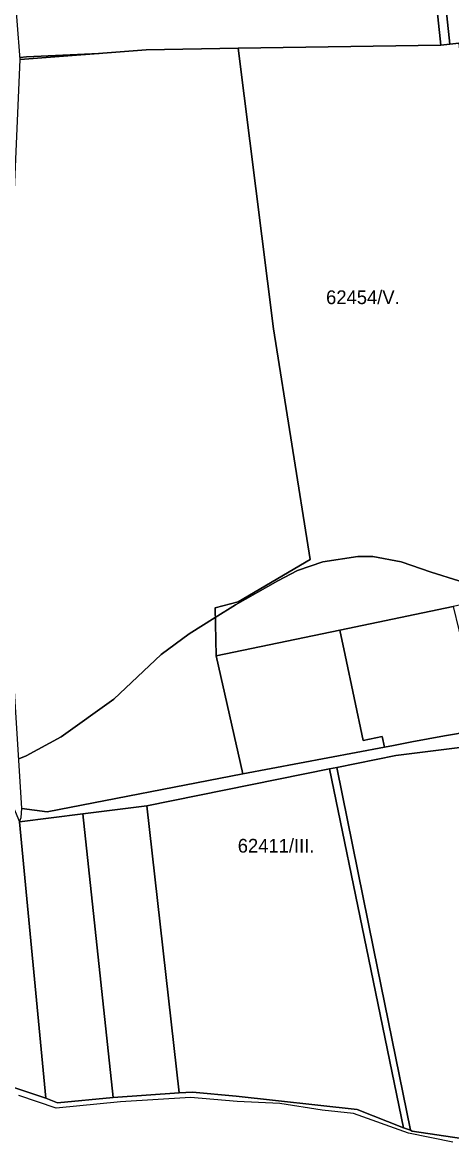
# Model space of a CAD drawing. Extents: x -502026 to -497664, y -1143484 to -1138019.
# Drawn here: x -501528 to -501278, y -1139303 to -1138651 of the extents above; entities that cross this region are included whole.
import ezdxf

# ---------------------------------------------------------------- set-up
doc = ezdxf.new("R2010")
doc.units = 0
for name, color, linetype in [('37', 7, 'Continuous'), ('43', 7, 'Continuous'), ('55', 7, 'Continuous'), ('62', 7, 'Continuous'), ('7', 7, 'Continuous')]:
    doc.layers.add(name, color=color, linetype=linetype)

msp = doc.modelspace()

# ---------------------------------------------------------------- linework, layer by layer
at = {"layer": '37'}
for points in [[(-501240.64, -1138808.67), (-501230.97, -1138846.49), (-501230.05, -1138850.09), (-501220.73, -1138886.54), (-501198.57, -1138973.2), (-501198.23, -1138974.54), (-501202.31, -1138975.39), (-501277.37, -1138991.02), (-501343.35, -1139004.77), (-501415.13, -1139019.72), (-501415.86, -1138991.76), (-501402.46, -1138988.23), (-501360.49, -1138963.6), (-501381.94, -1138829.32), (-501402.49, -1138666.06), (-501284.62, -1138664.16), (-501279.21, -1138663.65), (-501273.99, -1138663.16), (-501259.66, -1138801.19)], [(-501317.39, -1139072.9), (-501399.78, -1139088.42), (-501415.13, -1139019.72), (-501343.35, -1139004.77), (-501340.26, -1139019.42), (-501329.78, -1139069.07), (-501318.69, -1139066.73)]]:
    msp.add_lwpolyline(points, close=True, dxfattribs=at)
at = {"layer": '43'}
msp.add_lwpolyline([(-501273.99, -1138663.16), (-501279.21, -1138663.65), (-501298.15, -1138485.71), (-501344.57, -1138424.9), (-501372.1, -1138347.03), (-501386.23, -1138325.1), (-501447.01, -1138329.36), (-501473.69, -1138322.66), (-501491.71, -1138322.78), (-501541.29, -1138335.7), (-501509.5, -1138287.56), (-501489.51, -1138271.48), (-501466.16, -1138264.4), (-501362.59, -1138188.92), (-501294.09, -1138162.84), (-501292.08, -1138154.12), (-501292.08, -1138149.3), (-501273.99, -1138183.27)], dxfattribs=at)
msp.add_lwpolyline([(-501284.62, -1138664.16), (-501402.49, -1138666.06), (-501455.96, -1138667.04), (-501529.18, -1138672.63), (-501536.3, -1138582.4), (-501539, -1138511.42), (-501550.93, -1138448.55), (-501559.8, -1138369.69), (-501557.12, -1138355.92), (-501537.39, -1138339.47), (-501508.4, -1138331.68), (-501491.71, -1138328.26), (-501473.18, -1138328.27), (-501447.62, -1138335.21), (-501388.55, -1138331.19), (-501377.22, -1138347.03), (-501348.35, -1138427.58), (-501303.13, -1138488.15)], close=True, dxfattribs=at)
at = {"layer": '55'}
for points in [[(-501298.15, -1138485.71), (-501279.21, -1138663.65), (-501284.62, -1138664.16), (-501303.13, -1138488.15)], [(-501192.69, -1139063.02), (-501310.73, -1139077.78), (-501345.05, -1139084.74), (-501349.25, -1139085.57), (-501455.62, -1139107.1), (-501492.8, -1139111.78), (-501529.57, -1139116.45), (-501528.72, -1139113.96), (-501528.25, -1139108.55), (-501513.49, -1139110.5), (-501399.78, -1139088.42), (-501317.39, -1139072.9), (-501312.11, -1139071.91), (-501301.5, -1139069.91), (-501282.39, -1139066.31), (-501267.53, -1139063.76)], [(-501535.84, -1139270.17), (-501514.26, -1139277.37), (-501507.52, -1139279.96), (-501475.14, -1139276.85), (-501436.8, -1139274.26), (-501428.9, -1139273.74), (-501403.68, -1139276.06), (-501333.12, -1139283.96), (-501306.22, -1139294.49), (-501302.22, -1139295.94), (-501301.14, -1139296.44), (-501272.54, -1139300.79)], [(-501277.48, -1139302.93), (-501303.31, -1139297.65), (-501335.35, -1139286.28), (-501353.64, -1139284.28), (-501378.26, -1139280.38), (-501403.01, -1139279.22), (-501430.12, -1139276.84), (-501470.79, -1139279.48), (-501508.37, -1139283.07), (-501530.03, -1139275.64)]]:
    msp.add_lwpolyline(points, dxfattribs=at)
msp.add_lwpolyline([(-501267.53, -1139063.76), (-501282.39, -1139066.31), (-501301.5, -1139069.91), (-501312.11, -1139071.91), (-501317.39, -1139072.9), (-501318.69, -1139066.73), (-501329.78, -1139069.07), (-501340.26, -1139019.42), (-501343.35, -1139004.77), (-501277.37, -1138991.02), (-501274.06, -1139004.65), (-501267.08, -1139033.41), (-501263.12, -1139049.39), (-501270.32, -1139051.13), (-501269.13, -1139056.51)], close=True, dxfattribs=at)
at = {"layer": '62'}
for points in [[(-501529.27, -1138671.49), (-501525.59, -1138671), (-501483.19, -1138669), (-501481.11, -1138668.96), (-501455.96, -1138667.04), (-501402.49, -1138666.06), (-501284.62, -1138664.16), (-501279.21, -1138663.65), (-501273.99, -1138663.16)], [(-501273.99, -1138663.16), (-501279.21, -1138663.65), (-501284.62, -1138664.16), (-501402.49, -1138666.06), (-501455.96, -1138667.04), (-501481.11, -1138668.96), (-501483.19, -1138669), (-501525.59, -1138671), (-501529.27, -1138671.49)], [(-501530.03, -1139079.79), (-501525.81, -1139078), (-501505.41, -1139067), (-501474.69, -1139045), (-501447.31, -1139019), (-501430.91, -1139007), (-501415.71, -1138997.43), (-501403.91, -1138990), (-501379.41, -1138976), (-501368, -1138970), (-501353.19, -1138965), (-501332.91, -1138962), (-501324.09, -1138962), (-501307.59, -1138965), (-501290.09, -1138971), (-501274, -1138976)], [(-501274, -1138976), (-501290.09, -1138971), (-501307.59, -1138965), (-501324.09, -1138962), (-501332.91, -1138962), (-501353.19, -1138965), (-501368, -1138970), (-501379.41, -1138976), (-501403.91, -1138990), (-501415.71, -1138997.43), (-501430.91, -1139007), (-501447.31, -1139019), (-501474.69, -1139045), (-501505.41, -1139067), (-501525.81, -1139078), (-501530.03, -1139079.79)], [(-501277.48, -1139302.93), (-501303.31, -1139297.65), (-501335.35, -1139286.28), (-501353.64, -1139284.28), (-501378.26, -1139280.38), (-501403.01, -1139279.22), (-501430.12, -1139276.84), (-501470.79, -1139279.48), (-501508.37, -1139283.07), (-501530.03, -1139275.64)]]:
    msp.add_lwpolyline(points, dxfattribs=at)
at = {"layer": '7'}
for points in [[(-501415.13, -1139019.72), (-501399.78, -1139088.42), (-501513.49, -1139110.5), (-501528.25, -1139108.55), (-501538.47, -1138943.81), (-501538.29, -1138892.61), (-501536.93, -1138851), (-501529.18, -1138672.63), (-501455.96, -1138667.04), (-501402.49, -1138666.06), (-501381.94, -1138829.32), (-501360.49, -1138963.6), (-501402.46, -1138988.23), (-501415.86, -1138991.76)], [(-500988.99, -1139154.62), (-500980.11, -1139197.63), (-500989.97, -1139217.3), (-500998.17, -1139222.39), (-501035.85, -1139237.77), (-501089.19, -1139253.97), (-501087.64, -1139266.82), (-501134.05, -1139276.74), (-501214.12, -1139297.82), (-501243.68, -1139303.15), (-501272.54, -1139300.79), (-501301.14, -1139296.44), (-501302.22, -1139295.94), (-501323.63, -1139190.19), (-501345.05, -1139084.74), (-501310.73, -1139077.78), (-501192.69, -1139063.02), (-501168.72, -1139072.15), (-501122.47, -1139094.84)], [(-501529.57, -1139116.45), (-501514.26, -1139277.37), (-501535.84, -1139270.17), (-501552.12, -1139106.08), (-501554.18, -1139085.36), (-501547.97, -1139086.51), (-501540.74, -1139090.09)], [(-501306.22, -1139294.49), (-501333.12, -1139283.96), (-501403.68, -1139276.06), (-501428.9, -1139273.74), (-501436.8, -1139274.26), (-501455.62, -1139107.1), (-501349.25, -1139085.57), (-501327.84, -1139190)], [(-501302.22, -1139295.94), (-501306.22, -1139294.49), (-501327.84, -1139190), (-501349.25, -1139085.57), (-501345.05, -1139084.74), (-501323.63, -1139190.19)], [(-501436.8, -1139274.26), (-501475.14, -1139276.85), (-501492.8, -1139111.78), (-501455.62, -1139107.1)], [(-501475.14, -1139276.85), (-501507.52, -1139279.96), (-501514.26, -1139277.37), (-501529.57, -1139116.45), (-501492.8, -1139111.78)]]:
    msp.add_lwpolyline(points, close=True, dxfattribs=at)

# ---------------------------------------------------------------- texts
at = {"layer": '62'}
for s, p in [('62454/V.', (-501351.29, -1138814.99)), ('62411/III.', (-501402.67, -1139134.32))]:
    msp.add_text(s, height=8, dxfattribs=at).set_placement(p)

doc.saveas('drawing.dxf')
